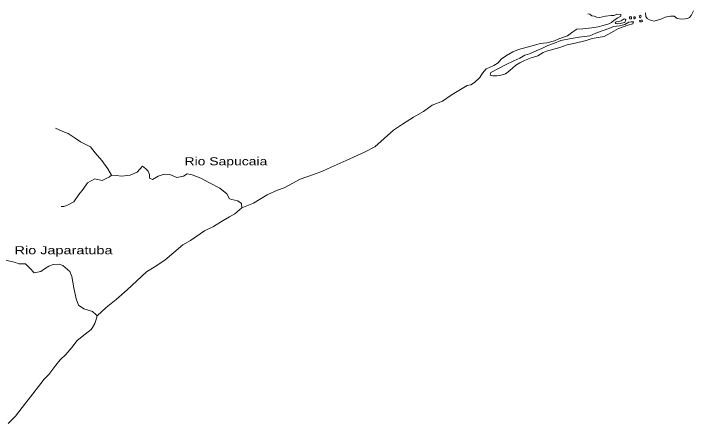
# Model space of a CAD drawing. Extents: x 47169 to 972804, y 7447977 to 9608469.
# Drawn here: x 726866 to 783917, y 8802083 to 8836489 of the extents above; entities that cross this region are included whole.
import ezdxf

# ---------------------------------------------------------------- set-up
doc = ezdxf.new("R2010")
doc.units = 0
doc.header["$LTSCALE"] = 270
doc.layers.add('1', color=7, linetype='Continuous', lineweight=13)
doc.layers.add('3', color=7, linetype='Continuous')

msp = doc.modelspace()

# ---------------------------------------------------------------- linework, layer by layer
at = {"layer": '1'}
for points in [[(783916.8, 8836718.7), (783727.4, 8836332.9), (783594.6, 8836168), (783407.7, 8836081), (783232.1, 8836038.2), (782925.3, 8836029.6), (782564.3, 8836087.9), (782313.9, 8836267.1), (782007.2, 8836269.6), (781535.6, 8836196), (781183.6, 8836010.7), (780634.6, 8835849.2), (780230.2, 8835952.1), (780023.1, 8836075.6), (779925.9, 8836253.4), (779895.4, 8836541.4)], [(766220, 8831493), (766529.4, 8831844.7), (766814.9, 8831953.2), (767166.7, 8832127.5), (767529.8, 8832346), (767795, 8832653.8), (768224.6, 8832971.4), (768774.5, 8833265.9), (769247.1, 8833483.5), (770695.8, 8833870.5), (771047, 8833967.3), (771606.1, 8834040.4), (772253.6, 8834201.3), (772616.3, 8834364.4), (773363.1, 8834624.1), (773792.9, 8834963.7), (774145.2, 8835182.2), (774638.2, 8835200.4), (775405.5, 8835282.8), (775932.1, 8835389.3), (776338.2, 8835496.7), (776832.1, 8835625.5), (777041.2, 8835745.6), (777272.8, 8835942.9), (777581, 8836128.6), (777823, 8836259.4), (777824.3, 8836425.4), (777495.9, 8836450.2), (777264.9, 8836330.4), (777024, 8836332.3), (776530.7, 8836280.9), (776047.7, 8836152), (775807.1, 8836198.2), (775599.6, 8836266.3), (775380.9, 8836312.3), (775228.5, 8836435.3), (775053.6, 8836469.9)], [(726419.5, 8802083.3), (727036.2, 8802698.7), (727577.1, 8803414.2), (728294.3, 8804316.6), (729155.2, 8805428.2), (729420.2, 8805791.5), (729816.8, 8806198.2), (730423.8, 8806968.5), (730777, 8807419.7), (731239.7, 8807881.2), (731747, 8808464.2), (732199.5, 8809036.4), (732870.7, 8809585), (733387.6, 8809968.7), (733487.2, 8810122.9), (733686.5, 8810464.5), (733775.8, 8810718.4), (733888, 8811115.9), (734636.9, 8811818.8), (735473.3, 8812499), (736398.2, 8813311.3), (738017.4, 8814815.8), (738676.8, 8815209.5), (739556.3, 8815778.6), (741075.8, 8817084.6), (741702.1, 8817434.2), (742901, 8818255.5), (743647.9, 8818626.3), (744461.3, 8819107.3), (744988.9, 8819424.4), (745428.5, 8819664.7), (746023.3, 8820180.4), (747000.3, 8820571.7), (748132.8, 8821271.6), (749022.2, 8821652.4), (749582.1, 8821869.6), (750922.8, 8822579), (752042.3, 8822969), (752788.9, 8823273.3), (753524.7, 8823588.8), (754766.1, 8824166), (756325.9, 8824862.5), (757172.2, 8825309.8), (758748.4, 8826703.3), (759496.7, 8827195.6), (760420.9, 8827797.2), (761256.8, 8828277.7), (761994.5, 8828814.3), (762873, 8829150.6), (763665.5, 8829686.8), (764919.8, 8830451.8), (765248.8, 8830515.6), (765545.9, 8830701.4), (765987.1, 8831118.5), (766220, 8831493)], [(746023.3, 8820180.4), (745982.2, 8820545.9), (745688.3, 8820780.4), (745185.6, 8820883.6), (744989, 8820951.4), (744762.2, 8821362.5), (744174.6, 8821842.6), (743258.5, 8822313.9), (742571.5, 8822684), (741840.2, 8822965.8), (741435.6, 8823024), (741138.6, 8822827), (740557.7, 8822720.4), (739979.4, 8822979), (739498, 8823004.6), (739004.2, 8822831), (738531.6, 8822557.7), (738280.6, 8822659.1), (738260.9, 8822980.1), (738164.3, 8823246.3), (737968.7, 8823446.8), (737696.7, 8823692.2), (737233.4, 8823175.4), (736651.6, 8822936), (735928.4, 8822830.4), (735502, 8822888.7), (735086.2, 8822913.7), (734761.5, 8823447.1), (734262.8, 8824147.6), (733698.1, 8824793.2), (733329.4, 8825304.7), (732489.5, 8825730.9), (732031.7, 8826021.7), (731432.5, 8826435.2), (731006.7, 8826593), (730384.5, 8826862.8)], [(735086.2, 8822913.7), (734921, 8822771), (734306, 8822465.4), (733694, 8822613.5), (733067.8, 8822274.8), (732692, 8821735.2), (732349.8, 8821306.1), (731918.6, 8820678.3), (731325.5, 8820372.6), (731073.2, 8820285.8), (730865.2, 8820287.2)], [(733888, 8811115.9), (733801.1, 8811205), (733496.6, 8811472.7), (733049, 8811619.7), (732765, 8811699.1), (732318.6, 8812012), (732103.5, 8812555.6), (731912.9, 8813475.3), (731755.2, 8814405.8), (731583.1, 8814838.5), (731006.5, 8815340.4), (730701, 8815464.2), (730175.4, 8815423.5), (729813.3, 8815271.1), (729461.6, 8815052.2), (729142.9, 8814844.1), (728584.1, 8814737.3), (728225.5, 8815115.9), (728051.5, 8815272), (727866.9, 8815483.5), (727308.9, 8815487.2), (727025.1, 8815599.8), (726216.6, 8815782.2)]]:
    msp.add_lwpolyline(points, dxfattribs=at)
for points in [[(777633.3, 8835829.3), (777863.7, 8835871.8), (778095, 8836035.9), (778182.6, 8836035.2), (778236.8, 8835968.3), (778158.4, 8835747.6), (777894.9, 8835672.3), (777774.2, 8835651.1), (777544, 8835619.8), (777412.8, 8835654), (777380.1, 8835676.4), (777348.1, 8835776.3), (777468.7, 8835786.4)], [(778620.6, 8836020.6), (778598.9, 8836042.9), (778555.4, 8836087.5), (778556, 8836153.9), (778556.4, 8836209.2), (778622.3, 8836230.8), (778655.2, 8836230.6), (778731.7, 8836207.8), (778730.4, 8836052.9)], [(779037.5, 8836105.7), (778982.3, 8836050.8), (778927.8, 8836084.5), (778928.8, 8836206.2), (778994.7, 8836227.8), (779027.6, 8836227.6), (779059.9, 8836160.9)], [(779400, 8836235.6), (779378.8, 8836313.2), (779455.6, 8836334.7), (779510.5, 8836345.4), (779531.6, 8836256.7), (779486.8, 8836135.3), (779410.2, 8836135.9), (779399.8, 8836202.4)], [(773646.1, 8834400.4), (774326, 8834516.8), (775225, 8834631.3), (775719.6, 8834848.7), (776247, 8835054.7), (776807, 8835227.3), (777224.6, 8835401), (777718.1, 8835474.5), (778156.9, 8835570.5), (778487, 8835756), (778706.4, 8835798.5), (778859.8, 8835797.3), (778892.5, 8835785.9), (778836.6, 8835642.5), (778408.5, 8835524.2), (777628.5, 8835231.7), (777243.4, 8835024.6), (776429.3, 8834566.3), (775409.3, 8834397.4), (774904.1, 8834224.4), (773894.6, 8833977.9), (773335.1, 8833860.6), (772709.2, 8833655.3), (771600.6, 8833343.2), (771314.8, 8833212.7), (770852.8, 8832950.7), (770292.9, 8832778.1), (769732.5, 8832539), (769347.7, 8832342.8), (769028.5, 8832146.1), (768521.4, 8831718.5), (768146.8, 8831422.6), (767674.8, 8831282.4), (767411.9, 8831273.4), (767072.5, 8831276.1), (766864.7, 8831310.9), (766921.2, 8831531.8), (767668.9, 8831924.4), (768141.7, 8832175.2), (768845.2, 8832512.8), (769339.8, 8832741.3), (769769, 8833003.5), (770153.2, 8833122.2), (770713.7, 8833372.3), (771186.2, 8833567.8), (771702.9, 8833818.3), (772262.9, 8834002), (772801.5, 8834241.2)], [(779571.7, 8835791.5), (779462.1, 8835792.4), (779407.7, 8835837.1), (779397.3, 8835903.6), (779441.2, 8835914.3), (779528.9, 8835924.6), (779583.7, 8835924.2), (779616.6, 8835923.9), (779648.6, 8835824)]]:
    msp.add_lwpolyline(points, close=True, dxfattribs=at)

# ---------------------------------------------------------------- texts
at = {"layer": '3'}
for s, height, width, p in [('Rio Sapucaia', 671.9, 1.3, (741210.9, 8823755.9)), ('Rio Japaratuba', 671.7, 1.35, (726945.8, 8816286.6))]:
    msp.add_text(s, height=height, dxfattribs=dict(at, width=width)).set_placement(p)

doc.saveas('drawing.dxf')
